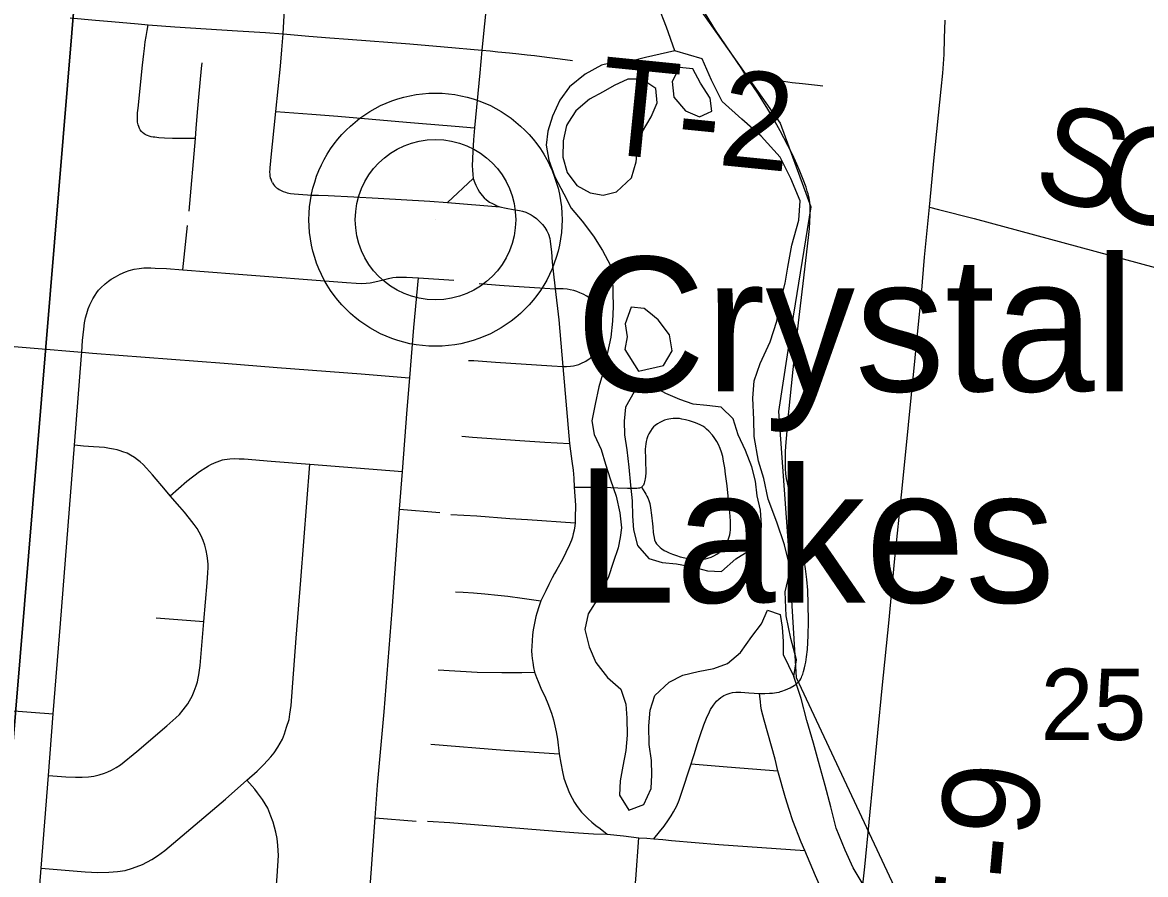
# Model space of a CAD drawing. Extents: x 0 to 1134, y 0 to 440.
# Drawn here: x 212.85 to 232.66, y 153.89 to 168.91 of the extents above; entities that cross this region are included whole.
import ezdxf

# ---------------------------------------------------------------- set-up
doc = ezdxf.new("R2010")
doc.units = 0
for name, color, linetype in [('GM_X_Minor_Lake', 7, 'Continuous'), ('GM_X_Minor_River', 7, 'Continuous'), ('GM_X_Rail_Line', 7, 'Continuous'), ('GM_X_Section', 7, 'Continuous'), ('GM_X_Section_Text', 7, 'Continuous'), ('GM_X_Township_Road', 7, 'Continuous'), ('GM_X_Township_Road_Text', 7, 'Continuous'), ('GM_X_Unincorporated', 7, 'Continuous'), ('GM_X_Unincorporated_Location', 7, 'Continuous'), ('GM_X_Unincorporated_Text', 7, 'Continuous')]:
    doc.layers.add(name, color=color, linetype=linetype)

msp = doc.modelspace()

# ---------------------------------------------------------------- linework, layer by layer
at = {"layer": 'GM_X_Minor_Lake'}
for points in [[(224.436, 168.119), (224.307, 167.87), (224.338, 167.597), (224.54, 167.355), (224.789, 167.25), (224.929, 167.314)], [(224.929, 167.314), (225.006, 167.349), (224.975, 167.577), (224.807, 167.841), (224.674, 168.094), (224.436, 168.119)], [(224.021, 167.749), (223.773, 167.911), (223.523, 167.914), (223.283, 167.804), (223.088, 167.692), (222.847, 167.559), (222.606, 167.357), (222.48, 167.156)], [(222.48, 167.156), (222.443, 167.097), (222.383, 166.824), (222.38, 166.54), (222.456, 166.265), (222.623, 166.036), (222.861, 165.907), (223.088, 165.87), (223.327, 165.924), (223.592, 166.172), (223.675, 166.455), (223.702, 166.739), (223.784, 166.989), (223.936, 167.249), (224.041, 167.498), (224.021, 167.749)], [(223.896, 163.803), (223.814, 163.869), (223.587, 163.894), (223.48, 163.6), (223.512, 163.371), (223.475, 163.144), (223.716, 162.761)], [(223.716, 162.761), (224.154, 162.862), (224.305, 163.122), (224.263, 163.407), (224.062, 163.672), (223.896, 163.803)], [(223.869, 162.5), (223.636, 162.402), (223.485, 162.131), (223.459, 161.88), (223.467, 161.641), (223.51, 161.379), (223.54, 161.071), (223.57, 160.752), (223.601, 160.478), (223.609, 160.205), (223.628, 159.965), (223.693, 159.691), (223.895, 159.461), (224.133, 159.39), (224.383, 159.364), (224.667, 159.315), (224.928, 159.243), (225.178, 159.229), (225.431, 159.453), (225.651, 159.59)], [(225.651, 159.59), (225.718, 159.632), (225.869, 159.88), (225.882, 160.051), (225.863, 160.313), (225.809, 160.564), (225.778, 160.826), (225.713, 161.078), (225.603, 161.364), (225.47, 161.639), (225.382, 161.925), (225.169, 162.132), (224.919, 162.158), (224.68, 162.184), (224.442, 162.267), (224.193, 162.372), (223.945, 162.512), (223.869, 162.5)]]:
    msp.add_lwpolyline(points, dxfattribs=at)
at = {"layer": 'GM_X_Minor_River'}
for points in [[(227.747, 153.594), (227.502, 154.007), (227.358, 154.316), (227.203, 154.705), (227.106, 155.082), (227.008, 155.459), (226.888, 155.882), (226.801, 156.202), (226.681, 156.602), (226.583, 156.99), (226.452, 157.379), (226.501, 157.675), (226.403, 158.052), (226.317, 158.451), (226.3, 158.873), (226.396, 159.27), (226.287, 159.704), (226.156, 160.104), (226.002, 160.505), (225.926, 160.87), (225.828, 161.179), (225.754, 161.612), (225.746, 161.909), (225.728, 162.285), (225.755, 162.592), (225.861, 162.898), (226.036, 163.283), (226.154, 163.646), (226.204, 163.952), (226.299, 164.316), (226.348, 164.6), (226.421, 164.986), (226.541, 165.428), (226.568, 165.77), (226.402, 166.159), (226.213, 166.537), (225.877, 166.906), (225.539, 167.206), (225.19, 167.518), (225.002, 167.896), (224.836, 168.274), (224.354, 168.41), (224.205, 168.828), (224.062, 169.206)], [(224.354, 168.41), (223.835, 168.298), (223.584, 168.233), (223.333, 168.224), (223.06, 168.159), (222.773, 168.004), (222.497, 167.779), (222.324, 167.542), (222.195, 167.259), (222.112, 166.999), (222.086, 166.748), (222.129, 166.486), (222.239, 166.189), (222.394, 165.89), (222.528, 165.638), (222.718, 165.408), (222.92, 165.144), (223.076, 164.891), (223.22, 164.628), (223.252, 164.411), (223.26, 164.149), (223.268, 163.898), (223.254, 163.648), (223.227, 163.364), (223.167, 163.091), (223.095, 162.762), (223.012, 162.49), (222.951, 162.183), (222.89, 161.888), (222.933, 161.648), (223.055, 161.385), (223.131, 161.122), (223.219, 160.847), (223.317, 160.561), (223.382, 160.264), (223.413, 160.002), (223.388, 159.832), (223.352, 159.65), (223.269, 159.389), (223.186, 159.14), (223.022, 158.789), (222.825, 158.484), (222.765, 158.211), (222.841, 157.903), (222.962, 157.628), (223.164, 157.364), (223.4, 157.156), (223.488, 156.893), (223.507, 156.642), (223.515, 156.346), (223.489, 156.073), (223.44, 155.8), (223.391, 155.539), (223.377, 155.289), (223.544, 155.025), (223.807, 155.124), (223.936, 155.407), (223.95, 155.646), (223.942, 155.896), (223.9, 156.182), (223.893, 156.512), (223.919, 156.785), (224.002, 157.046), (224.255, 157.282), (224.495, 157.404), (224.769, 157.469), (225.043, 157.522), (225.283, 157.61), (225.513, 157.801), (225.71, 158.083), (225.883, 158.309), (225.988, 158.547), (226.215, 158.475), (226.246, 158.247), (226.266, 157.996), (226.263, 157.769), (226.452, 157.379)], [(226.452, 157.379), (226.501, 157.675), (226.403, 158.052), (226.317, 158.451), (226.3, 158.873), (226.396, 159.27), (226.287, 159.704), (226.156, 160.104), (226.002, 160.505), (225.926, 160.87), (225.828, 161.179), (225.754, 161.612), (225.746, 161.909), (225.728, 162.285), (225.755, 162.592), (225.861, 162.898), (226.036, 163.283), (226.154, 163.646), (226.204, 163.952), (226.299, 164.316), (226.348, 164.6), (226.421, 164.986), (226.541, 165.428), (226.568, 165.77), (226.402, 166.159), (226.213, 166.537), (225.877, 166.906), (225.539, 167.206), (225.19, 167.518), (225.002, 167.896), (224.836, 168.274), (224.354, 168.41)]]:
    msp.add_lwpolyline(points, dxfattribs=at)
at = {"layer": 'GM_X_Rail_Line'}
msp.add_lwpolyline([(221.797, 245.364), (221.181, 240.333), (221.128, 239.013), (217.027, 199.63), (217.027, 198.85), (222.212, 177.253), (223.614, 172.593), (224.567, 169.474), (226.214, 167.135), (226.756, 165.662), (226.412, 163.551), (226.185, 162.05), (226.353, 159.693), (226.495, 157.362), (232.797, 143.924), (233.602, 142.873), (234.295, 142.479), (235.537, 142.526)], dxfattribs=at)
at = {"layer": 'GM_X_Section'}
for points in [[(183.714, 176.72), (183.741, 176.98), (214.176, 174.272), (211.65, 143.881), (181.082, 146.67)], [(214.176, 174.272), (244.499, 171.089), (241.786, 141.042), (212.603, 143.785), (211.65, 143.881)]]:
    msp.add_lwpolyline(points, close=True, dxfattribs=at)
at = {"layer": 'GM_X_Township_Road'}
for p, q in [((221.084, 169.786), (220.947, 168.426)), ((215.789, 165.584), (215.896, 166.864)), ((220.342, 165.737), (220.798, 166.163)), ((220.342, 165.737), (221.266, 165.661)), ((215.675, 164.551), (215.755, 165.333)), ((219.831, 164.407), (220.455, 164.368)), ((222.376, 162.848), (222.495, 161.487)), ((217.914, 161.124), (219.548, 160.996)), ((219.495, 160.33), (219.548, 160.996)), ((219.495, 160.33), (220.208, 160.273)), ((215.206, 158.416), (216.046, 158.352)), ((213.304, 155.634), (213.389, 156.721)), ((213.176, 154), (213.304, 155.634)), ((219.068, 154.886), (219.79, 154.827))]:
    msp.add_line(p, q, dxfattribs=at)
for points in [[(217.446, 168.713), (217.48, 169.362), (217.519, 169.885), (217.533, 170.04)], [(225.627, 167.949), (225.534, 168.098), (225.069, 168.779), (224.833, 169.17), (224.713, 169.4)], [(213.689, 168.997), (214.131, 168.955), (214.417, 168.931), (214.887, 168.886), (215.062, 168.872)], [(215.896, 166.864), (215.495, 166.867), (215.35, 166.873), (215.253, 166.88), (215.183, 166.888), (215.15, 166.892), (215.117, 166.899), (215.083, 166.909), (215.053, 166.919), (215.032, 166.927), (215.011, 166.937), (214.993, 166.949), (214.962, 166.974), (214.945, 166.993), (214.924, 167.017), (214.91, 167.042), (214.896, 167.076), (214.886, 167.107), (214.875, 167.154), (214.872, 167.185), (214.872, 167.208), (214.873, 167.248), (214.877, 167.32), (214.884, 167.401), (214.965, 168.16), (214.985, 168.36), (214.997, 168.454), (215.012, 168.573), (215.027, 168.663), (215.044, 168.773), (215.062, 168.872)], [(215.062, 168.872), (215.534, 168.834), (216.641, 168.767), (217.13, 168.734), (217.446, 168.713)], [(228.846, 165.657), (228.93, 166.533), (229.056, 167.738), (229.085, 168.018), (229.105, 168.346), (229.114, 168.634), (229.121, 168.954)], [(217.317, 167.345), (217.398, 168.141), (217.42, 168.429), (217.446, 168.713)], [(217.446, 168.713), (217.899, 168.671), (218.265, 168.643), (218.591, 168.618), (219.681, 168.537), (220.287, 168.484), (220.947, 168.426)], [(220.947, 168.426), (220.914, 168.026), (220.82, 167.056)], [(220.947, 168.426), (221.097, 168.411), (221.233, 168.397), (221.44, 168.375), (221.601, 168.358), (221.748, 168.342), (221.878, 168.328), (222.094, 168.299), (222.334, 168.269), (222.55, 168.241)], [(215.896, 166.864), (215.91, 167.045), (215.928, 167.263), (215.958, 167.594), (216.006, 168.1), (216.014, 168.202)], [(225.85, 157.081), (225.943, 157.081), (226.022, 157.084), (226.08, 157.087), (226.148, 157.096), (226.197, 157.106), (226.216, 157.113), (226.245, 157.122), (226.306, 157.146), (226.388, 157.18), (226.457, 157.219), (226.493, 157.242), (226.532, 157.278), (226.549, 157.296), (226.56, 157.312), (226.576, 157.339), (226.588, 157.364), (226.597, 157.385), (226.611, 157.423), (226.625, 157.467), (226.642, 157.531), (226.654, 157.585), (226.664, 157.635), (226.679, 157.726), (226.694, 157.858), (226.703, 157.982), (226.708, 158.104), (226.711, 158.348), (226.708, 158.663), (226.699, 158.9), (226.684, 159.093), (226.659, 159.281), (226.641, 159.393), (226.627, 159.48), (226.584, 159.702), (226.557, 159.825), (226.509, 160.03), (226.459, 160.243), (226.408, 160.467), (226.351, 160.739), (226.327, 160.869), (226.315, 160.955), (226.308, 161.049), (226.304, 161.15), (226.307, 161.255), (226.309, 161.355), (226.318, 161.51), (226.329, 161.642), (226.35, 161.879), (226.391, 162.276), (226.468, 163.021), (226.493, 163.263), (226.569, 163.914), (226.616, 164.31), (226.712, 165.123), (226.729, 165.277), (226.738, 165.401), (226.743, 165.511), (226.745, 165.587), (226.745, 165.657), (226.739, 165.743), (226.723, 165.815), (226.706, 165.889), (226.692, 165.94), (226.669, 166.01), (226.62, 166.141), (226.56, 166.292), (226.504, 166.415), (226.428, 166.584), (226.349, 166.744), (226.213, 167.001), (226.058, 167.278), (225.947, 167.462), (225.82, 167.669), (225.627, 167.949)], [(225.627, 167.949), (225.751, 167.946), (225.83, 167.943), (225.917, 167.933), (226.027, 167.921), (226.272, 167.877), (226.424, 167.855), (226.606, 167.834), (226.874, 167.806), (226.966, 167.798)], [(217.255, 166.085), (217.244, 166.109), (217.23, 166.147), (217.223, 166.169), (217.215, 166.206), (217.214, 166.237), (217.212, 166.274), (217.215, 166.329), (217.217, 166.361), (217.221, 166.4), (217.227, 166.481), (217.317, 167.345)], [(217.317, 167.345), (217.949, 167.295), (218.408, 167.26), (219.621, 167.157), (219.833, 167.14), (220.479, 167.086), (220.82, 167.056)], [(220.82, 167.056), (220.803, 166.844), (220.791, 166.651), (220.784, 166.5), (220.781, 166.39), (220.784, 166.309), (220.788, 166.231), (220.798, 166.163)], [(217.255, 166.085), (217.275, 166.055), (217.294, 166.03), (217.313, 166.011), (217.328, 165.998), (217.349, 165.984), (217.373, 165.969), (217.409, 165.949), (217.445, 165.933), (217.483, 165.92), (217.514, 165.909), (217.543, 165.902), (217.575, 165.897), (217.637, 165.89), (217.713, 165.885), (217.951, 165.868), (218.067, 165.865), (218.238, 165.859), (218.69, 165.839), (219.121, 165.815), (220.03, 165.763), (220.342, 165.737)], [(220.798, 166.163), (220.824, 166.087), (220.843, 166.041), (220.879, 165.974), (220.91, 165.921), (220.955, 165.859), (220.99, 165.822), (221.029, 165.787), (221.087, 165.746), (221.136, 165.718), (221.182, 165.697), (221.216, 165.68), (221.266, 165.661)], [(221.266, 165.661), (221.381, 165.636), (221.503, 165.614), (221.613, 165.596), (221.669, 165.583), (221.726, 165.565), (221.782, 165.541), (221.821, 165.521), (221.855, 165.499), (221.912, 165.457), (221.968, 165.406), (222.021, 165.348), (222.062, 165.295), (222.095, 165.24), (222.125, 165.178), (222.147, 165.101), (222.154, 165.058), (222.162, 165.006), (222.178, 164.869), (222.191, 164.687), (222.206, 164.528), (222.244, 164.218)], [(227.519, 152.317), (227.706, 154.021), (228.015, 157.174), (228.137, 158.379), (228.23, 159.4), (228.367, 160.697), (228.704, 164.124), (228.762, 164.773), (228.846, 165.657)], [(228.846, 165.657), (229.004, 165.617), (229.637, 165.455), (233.33, 164.456), (234.654, 164.108), (235.918, 163.767), (236.464, 163.612), (236.931, 163.488), (237.451, 163.355), (237.589, 163.324), (237.735, 163.295), (237.85, 163.276), (238.145, 163.233), (238.475, 163.189), (239.459, 163.063), (242.643, 162.631), (243.675, 162.5)], [(214.227, 164.235), (214.307, 164.305), (214.361, 164.349), (214.41, 164.384), (214.486, 164.43), (214.566, 164.475), (214.665, 164.518), (214.729, 164.54), (214.818, 164.564), (214.903, 164.577), (214.985, 164.585), (215.107, 164.584), (215.184, 164.582), (215.384, 164.575), (215.675, 164.551)], [(215.675, 164.551), (216.581, 164.478), (218.563, 164.329), (218.734, 164.316), (218.831, 164.311), (218.907, 164.314), (218.977, 164.32), (219.063, 164.339), (219.216, 164.377), (219.301, 164.397), (219.379, 164.415), (219.44, 164.422), (219.531, 164.422), (219.623, 164.42), (219.831, 164.407)], [(219.68, 162.644), (219.752, 163.534), (219.831, 164.407)], [(220.904, 164.309), (221.259, 164.282), (221.517, 164.262), (221.788, 164.246), (222.061, 164.229), (222.244, 164.218)], [(213.891, 163.099), (213.907, 163.306), (213.925, 163.506), (213.942, 163.619), (213.96, 163.705), (213.98, 163.778), (214.005, 163.861), (214.033, 163.934), (214.055, 163.979), (214.089, 164.04), (214.129, 164.106), (214.158, 164.15), (214.188, 164.192), (214.227, 164.235)], [(222.244, 164.218), (222.308, 163.667), (222.376, 162.848)], [(222.376, 162.848), (222.444, 162.848), (222.515, 162.854), (222.565, 162.859), (222.616, 162.868), (222.66, 162.883), (222.699, 162.9), (222.783, 162.943), (222.859, 162.995), (222.906, 163.035), (222.946, 163.072), (222.984, 163.12), (223.004, 163.156), (223.018, 163.189), (223.03, 163.229), (223.04, 163.272), (223.047, 163.325), (223.053, 163.403), (223.059, 163.49), (223.058, 163.596), (223.053, 163.656), (223.045, 163.714), (223.037, 163.76), (223.008, 163.847), (222.966, 163.927), (222.909, 163.999), (222.842, 164.06), (222.801, 164.086), (222.74, 164.123), (222.681, 164.148), (222.626, 164.17), (222.571, 164.185), (222.509, 164.198), (222.455, 164.208), (222.386, 164.215), (222.347, 164.217), (222.303, 164.218), (222.244, 164.218)], [(212.267, 163.237), (213.051, 163.169), (213.891, 163.099)], [(213.762, 161.459), (213.887, 163.041), (213.891, 163.099)], [(213.891, 163.099), (214.079, 163.083), (215.472, 162.977), (216.404, 162.903), (217.336, 162.829), (218.821, 162.716), (219.597, 162.651), (219.68, 162.644)], [(220.715, 162.953), (220.809, 162.95), (221.188, 162.925), (222.185, 162.856), (222.376, 162.848)], [(219.548, 160.996), (219.634, 162.088), (219.68, 162.644)], [(222.581, 160.719), (222.821, 160.72), (223.012, 160.718), (223.226, 160.713), (223.35, 160.708), (223.52, 160.701), (223.65, 160.7), (223.684, 160.701), (223.714, 160.704), (223.737, 160.709), (223.765, 160.719), (223.824, 160.624), (223.84, 160.597), (223.861, 160.562), (223.877, 160.528), (223.895, 160.484), (223.912, 160.431), (223.926, 160.355), (223.945, 160.224), (223.962, 160.073), (223.966, 160.017), (223.974, 159.927), (223.979, 159.883), (223.988, 159.83), (223.998, 159.789), (224.013, 159.751), (224.033, 159.72), (224.054, 159.693), (224.076, 159.671), (224.096, 159.652), (224.125, 159.629), (224.167, 159.603), (224.205, 159.583), (224.252, 159.56), (224.312, 159.535), (224.383, 159.511), (224.448, 159.491), (224.531, 159.47), (224.598, 159.461), (224.667, 159.451), (224.768, 159.444), (224.836, 159.447), (224.897, 159.456), (224.934, 159.464), (224.993, 159.485), (225.04, 159.506), (225.093, 159.538), (225.135, 159.568), (225.178, 159.609), (225.204, 159.639), (225.231, 159.672), (225.261, 159.719), (225.283, 159.761), (225.304, 159.81), (225.315, 159.844), (225.324, 159.876), (225.331, 159.92), (225.334, 159.967), (225.338, 160.037), (225.336, 160.113), (225.331, 160.209), (225.315, 160.385), (225.277, 160.741), (225.25, 160.945), (225.237, 161.058), (225.216, 161.178), (225.2, 161.261), (225.179, 161.336), (225.155, 161.403), (225.124, 161.47), (225.095, 161.526), (225.046, 161.597), (225.018, 161.633), (224.954, 161.708), (224.916, 161.743), (224.883, 161.769), (224.846, 161.794), (224.804, 161.816), (224.719, 161.854), (224.615, 161.889), (224.54, 161.908), (224.477, 161.919), (224.434, 161.927), (224.362, 161.929), (224.325, 161.929), (224.285, 161.926), (224.247, 161.92), (224.217, 161.912), (224.172, 161.898), (224.124, 161.878), (224.087, 161.859), (224.047, 161.835), (224.01, 161.806), (223.98, 161.78), (223.957, 161.755), (223.923, 161.705), (223.898, 161.659), (223.881, 161.624), (223.863, 161.573), (223.85, 161.526), (223.842, 161.482), (223.836, 161.434), (223.833, 161.389), (223.833, 161.353), (223.835, 161.25), (223.839, 161.146), (223.844, 161.016), (223.84, 160.955), (223.838, 160.925), (223.835, 160.904), (223.83, 160.865), (223.826, 160.839), (223.82, 160.811), (223.814, 160.786), (223.802, 160.755), (223.772, 160.724)], [(220.598, 161.619), (220.784, 161.602), (221.622, 161.541), (222.06, 161.514), (222.495, 161.487)], [(222.495, 161.487), (222.514, 161.356), (222.539, 161.179), (222.559, 161.018), (222.57, 160.88), (222.581, 160.719)], [(213.389, 156.721), (213.515, 158.315), (213.762, 161.459)], [(215.452, 160.568), (215.368, 160.666), (215.137, 160.935), (215.035, 161.052), (214.972, 161.117), (214.922, 161.164), (214.873, 161.203), (214.822, 161.242), (214.752, 161.284), (214.69, 161.315), (214.617, 161.344), (214.571, 161.361), (214.518, 161.375), (214.452, 161.39), (214.38, 161.402), (214.293, 161.415), (214.199, 161.423), (214.098, 161.432), (213.922, 161.444), (213.762, 161.459)], [(215.452, 160.568), (215.744, 160.824), (215.969, 160.992), (216.079, 161.067), (216.128, 161.096), (216.17, 161.119), (216.233, 161.147), (216.279, 161.168), (216.326, 161.184), (216.373, 161.198), (216.409, 161.206), (216.458, 161.214), (216.501, 161.218), (216.582, 161.222), (216.671, 161.22), (216.756, 161.216), (217.234, 161.178), (217.914, 161.124)], [(216.803, 155.55), (216.988, 155.713), (217.104, 155.827), (217.225, 155.965), (217.285, 156.035), (217.353, 156.131), (217.432, 156.274), (217.467, 156.369), (217.506, 156.484), (217.548, 156.621), (217.564, 156.716), (217.584, 156.868), (217.596, 157.027), (217.616, 157.266), (217.675, 158.055), (217.756, 159.081), (217.914, 161.124)], [(222.581, 160.719), (222.601, 160.4), (222.598, 160.173), (222.594, 160.092)], [(216.046, 158.352), (216.104, 159.034), (216.118, 159.205), (216.122, 159.299), (216.122, 159.353), (216.118, 159.42), (216.106, 159.506), (216.087, 159.603), (216.061, 159.694), (216.032, 159.78), (215.999, 159.859), (215.963, 159.925), (215.926, 159.988), (215.873, 160.061), (215.791, 160.168), (215.701, 160.278), (215.623, 160.369), (215.452, 160.568)], [(219.068, 154.886), (219.111, 155.466), (219.224, 156.757), (219.365, 158.543), (219.466, 159.937), (219.495, 160.33)], [(220.402, 160.238), (220.863, 160.21), (221.444, 160.167), (221.753, 160.146), (222.594, 160.092)], [(222.594, 160.092), (222.588, 160.035), (222.576, 159.958), (222.563, 159.898), (222.548, 159.838), (222.529, 159.786), (222.494, 159.701), (222.433, 159.566), (222.373, 159.441), (222.274, 159.267), (222.232, 159.196), (222.188, 159.119), (222.131, 159.004), (222.076, 158.89), (221.99, 158.712)], [(220.482, 158.875), (220.621, 158.868), (220.801, 158.854), (221.003, 158.837), (221.231, 158.816), (221.407, 158.797), (221.661, 158.762), (221.99, 158.712)], [(221.99, 158.712), (221.955, 158.611), (221.921, 158.497), (221.904, 158.439), (221.89, 158.379), (221.87, 158.288), (221.856, 158.2), (221.845, 158.115), (221.835, 158.006), (221.83, 157.917), (221.828, 157.835), (221.833, 157.753), (221.837, 157.695), (221.847, 157.627), (221.863, 157.538), (221.88, 157.457)], [(213.304, 155.634), (213.611, 155.613), (213.782, 155.603), (213.9, 155.603), (214.011, 155.61), (214.102, 155.624), (214.199, 155.648), (214.292, 155.677), (214.349, 155.698), (214.415, 155.728), (214.501, 155.776), (214.574, 155.823), (214.863, 156.056), (215.39, 156.512), (215.551, 156.653), (215.613, 156.712), (215.68, 156.789), (215.722, 156.843), (215.763, 156.9), (215.794, 156.953), (215.837, 157.033), (215.875, 157.12), (215.912, 157.217), (215.934, 157.285), (215.947, 157.348), (215.959, 157.41), (215.97, 157.492), (215.98, 157.571), (216.046, 158.352)], [(220.182, 157.495), (220.869, 157.456), (221.301, 157.452), (221.654, 157.45), (221.88, 157.457)], [(221.88, 157.457), (221.914, 157.362), (221.943, 157.29), (221.993, 157.172), (222.07, 157.001), (222.112, 156.905), (222.176, 156.732), (222.211, 156.618), (222.261, 156.402), (222.285, 156.274), (222.315, 156.017)], [(224.644, 155.837), (224.674, 155.936), (224.699, 156.021), (224.75, 156.183), (224.806, 156.355), (224.865, 156.526), (224.901, 156.616), (224.926, 156.675), (224.946, 156.717), (224.984, 156.795), (225.034, 156.876), (225.089, 156.944), (225.128, 156.979), (225.164, 157.007), (225.22, 157.044), (225.28, 157.071), (225.333, 157.087), (225.374, 157.095), (225.432, 157.101), (225.518, 157.103), (225.659, 157.091), (225.85, 157.081)], [(226.172, 155.715), (226.122, 155.922), (225.93, 156.61), (225.905, 156.698), (225.885, 156.787), (225.872, 156.865), (225.864, 156.931), (225.85, 157.081)], [(211.699, 156.849), (212.062, 156.823), (213.389, 156.721)], [(220.048, 156.188), (221.35, 156.083), (222.315, 156.017)], [(222.315, 156.017), (222.341, 155.852), (222.372, 155.699), (222.398, 155.587), (222.442, 155.459), (222.497, 155.321), (222.541, 155.237), (222.584, 155.16), (222.632, 155.088), (222.71, 154.99), (222.765, 154.926), (222.824, 154.87), (222.891, 154.811), (222.959, 154.755), (223.035, 154.697), (223.161, 154.597)], [(223.983, 154.519), (224.084, 154.638), (224.165, 154.743), (224.244, 154.853), (224.291, 154.925), (224.332, 154.994), (224.388, 155.101), (224.43, 155.2), (224.467, 155.307), (224.644, 155.837)], [(224.644, 155.837), (225.277, 155.784), (226.172, 155.715)], [(213.176, 154), (213.949, 153.936), (214.177, 153.923), (214.368, 153.927), (214.52, 153.939), (214.659, 153.959), (214.786, 153.997), (214.96, 154.064), (215.126, 154.15), (215.229, 154.218), (215.355, 154.312), (216.427, 155.219), (216.803, 155.55)], [(217.177, 151.795), (217.29, 153.171), (217.317, 153.553), (217.34, 153.86), (217.353, 154.043), (217.361, 154.222), (217.353, 154.397), (217.337, 154.525), (217.317, 154.637), (217.269, 154.808), (217.229, 154.919), (217.173, 155.055), (217.082, 155.21), (216.994, 155.33), (216.943, 155.394), (216.803, 155.55)], [(226.648, 154.31), (226.583, 154.461), (226.437, 154.832), (226.37, 155.033), (226.307, 155.238), (226.172, 155.715)], [(218.816, 151.656), (218.959, 153.424), (219.068, 154.886)], [(219.992, 154.831), (220.386, 154.805), (221.037, 154.755), (222.416, 154.641), (222.655, 154.624), (222.918, 154.606), (223.161, 154.597)], [(223.161, 154.597), (223.447, 154.568), (223.718, 154.536)], [(223.605, 153.151), (223.665, 153.806), (223.718, 154.536)], [(223.718, 154.536), (223.862, 154.526), (223.983, 154.519)], [(223.983, 154.519), (224.14, 154.508), (224.295, 154.489), (225.131, 154.415), (226.648, 154.31)], [(227.271, 152.882), (226.839, 153.862), (226.648, 154.31)], [(213.028, 152.13), (213.046, 152.354), (213.176, 154)]]:
    msp.add_lwpolyline(points, dxfattribs=at)
at = {"layer": 'GM_X_Unincorporated'}
for radius in [2.232, 1.415]:
    msp.add_circle((220.132, 165.435), radius, dxfattribs=at)
at = {"layer": 'GM_X_Unincorporated_Location'}
msp.add_line((220.132, 165.435), (220.132, 165.435), dxfattribs=at)

# ---------------------------------------------------------------- texts
at = {"layer": 'GM_X_Section_Text'}
msp.add_text('25', height=1.2557, rotation=0, dxfattribs=at).set_placement((230.807, 156.261))
at = {"layer": 'GM_X_Township_Road_Text'}
for s, height, rotation, p in [('T-2', 1.7045, 354.2903, (222.951, 166.619)), ('S', 1.705, 344.926, (230.613, 165.905)), ('C', 1.705, 344.928, (231.723, 165.606)), ('T-9', 1.7045, 84.7627, (230.528, 152.364))]:
    msp.add_text(s, height=height, rotation=rotation, dxfattribs=at).set_placement(p)
at = {"layer": 'GM_X_Unincorporated_Text'}
for s, p in [('Crystal', (222.607, 162.408)), ('Lakes', (222.607, 158.683))]:
    msp.add_text(s, height=2.3693, rotation=0, dxfattribs=at).set_placement(p)

doc.saveas('drawing.dxf')
